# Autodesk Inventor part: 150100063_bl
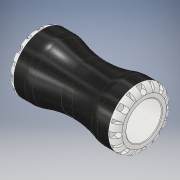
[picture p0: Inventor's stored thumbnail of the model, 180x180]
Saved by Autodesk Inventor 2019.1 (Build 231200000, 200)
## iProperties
Created: 2016-12
Part Number: 150100063_bl
Material: PVC-Piping
Description: PLASSON G-PLASS COUPLING 63X63
Document SubType Name: Modeling
Designer: KIM
Mass: 95.2094 g
Surface Area: 200.83 cm^2
Volume: 68.0067 cm^3
Density: 1.4 g/cm^3
Appearance: White
ILogicFactory: False
Author: KIM
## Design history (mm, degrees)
derived "150100.ipt"
feature "Solid1::150100.ipt" dims "ScaleForDerivedMember" = 10
tag "TaggingFeature1"
body "Solid1"
other parameters: "d2" = 95 [user parameter], "d4" = 5.25 [user parameter], "d11" = 9.7 [user parameter], "d13" = 9.7 [user parameter], "d14" = 0 [user parameter], "d16" = 360 deg [user parameter], "d18" = 8 deg [user parameter], "d19" = 1.26 [user parameter], "d20" = 8 deg [user parameter], "d21" = 1.26 [user parameter], "d23" = 0 [user parameter], "d25" = 360 deg [user parameter], "d27" = 41.2 [user parameter], "d28" = 15.75 [user parameter], "d29" = 18.9 [user parameter], "d30" = 18.9 [user parameter], "d31" = 0 [user parameter], "d33" = 0 [user parameter], "d37" = 38.4 [user parameter], "d38" = 1.03 [user parameter], "d43" = 7.875 [user parameter], "d44" = 63 [user parameter], "d45" = 38.4 [user parameter], "d46" = 82.4 [user parameter], "d47" = 103 [user parameter], "d48" = 192 [user parameter], "d50" = 360 deg [user parameter], "d54" = 0.513 [user parameter], "d_" = 63 [user parameter], "E_" = 103 [user parameter], "H_" = 192 [user parameter], "l_" = 95 [user parameter], "d12" = 78.75 [user parameter], "d42" = 103 [user parameter], "d52" = 12.125 [user parameter]
